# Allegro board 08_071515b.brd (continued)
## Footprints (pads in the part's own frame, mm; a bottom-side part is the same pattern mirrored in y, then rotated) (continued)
LSML208W216H122
  rect 1.168x4.394 smd: 1(-1.651,0) 2(1.651,0)
LSMSQ157H83_A
  rect 0.965x3.708 smd: 1(-1.181,0) 2(1.181,0)
LSMSQ157H122
  rect 0.965x3.708 smd: 1(-1.181,0) 2(1.181,0)
QFN12_2X2_PAD0_7X0_7
  oval 0.279x0.711 smd: 1(-0.75,-0.906) 2(-0.25,-0.906) 3(0.25,-0.906) 4(0.75,-0.906) 7(0.75,0.906) 8(0.25,0.906) 9(-0.25,0.906) 10(-0.75,0.906)
  oval 0.711x0.279 smd: 5(0.906,-0.25) 6(0.906,0.25) 11(-0.906,0.25) 12(-0.906,-0.25)
  rect 0.711x0.711 smd: PAD(0,0)
QFN14_3_5X3_5_PAD2_05X2_05
  oval 0.889x0.305 smd: 1(-1.7,-0.75) 7(1.7,-0.75) 8(1.7,0.75) 14(-1.7,0.75)
  oval 0.305x0.889 smd: 2(-1,-1.7) 3(-0.5,-1.7) 4(0,-1.7) 5(0.5,-1.7) 6(1,-1.7) 9(1,1.7) 10(0.5,1.7) 11(0,1.7) 12(-0.5,1.7) 13(-1,1.7)
  rect 2.057x2.057 smd: PAD(0,0)
QFN18_3X3_PAD1_51X1_7
  oval 0.279x0.711 smd: 1(-1,-1.406) 2(-0.5,-1.406) 3(0,-1.406) 4(0.5,-1.406) 5(1,-1.406) 10(1,1.406) 11(0.5,1.406) 12(0,1.406) 13(-0.5,1.406) 14(-1,1.406)
  oval 0.711x0.279 smd: 6(1.371,-0.75) 7(1.371,-0.25) 8(1.371,0.25) 9(1.371,0.75) 15(-1.371,0.75) 16(-1.371,0.25) 17(-1.371,-0.25) 18(-1.371,-0.75)
  rect 1.499x1.702 smd: PAD(0,0)
QFN24_4X4_PAD2_1X2_1
  oval 0.305x0.991 smd: 1(-1.25,-2) 2(-0.75,-2) 3(-0.25,-2) 4(0.25,-2) 5(0.75,-2) 6(1.25,-2) 13(1.25,2) 14(0.75,2) 15(0.25,2) 16(-0.25,2) 17(-0.75,2) 18(-1.25,2)
  oval 0.991x0.305 smd: 7(2,-1.25) 8(2,-0.75) 9(2,-0.25) 10(2,0.25) 11(2,0.75) 12(2,1.25) 19(-2,1.25) 20(-2,0.75) 21(-2,0.25) 22(-2,-0.25) 23(-2,-0.75) 24(-2,-1.25)
  rect 2.108x2.108 smd: PAD(0,0)
QFN28_5X5_PAD3_5X3_5
  oval 0.305x0.838 smd: 1(-1.5,-2.45) 2(-1,-2.45) 3(-0.5,-2.45) 4(0,-2.45) 5(0.5,-2.45) 6(1,-2.45) 7(1.5,-2.45) 15(1.5,2.45) 16(1,2.45) 17(0.5,2.45) 18(0,2.45) 19(-0.5,2.45) 20(-1,2.45) 21(-1.5,2.45)
  oval 0.838x0.305 smd: 8(2.45,-1.5) 9(2.45,-1) 10(2.45,-0.5) 11(2.45,0) 12(2.45,0.5) 13(2.45,1) 14(2.45,1.5) 22(-2.45,1.5) 23(-2.45,1) 24(-2.45,0.5) 25(-2.45,0) 26(-2.45,-0.5) 27(-2.45,-1) 28(-2.45,-1.5)
  rect 3.505x3.505 smd: PAD(0,0)
R0402
  rect 0.635x0.737 smd: 1(-0.5,0) 2(0.5,0)
R0603
  rect 0.787x0.991 smd: 1(-0.85,0) 2(0.85,0)
R0805
  rect 1.041x1.397 smd: 1(-0.95,0) 2(0.95,0)
RESNET8
  rect 0.533x0.813 smd: 1(-0.89,-0.606) 4(0.89,-0.606) 5(0.89,0.606) 8(-0.89,0.606)
  rect 0.254x0.813 smd: 2(-0.25,-0.606) 3(0.25,-0.606) 6(0.25,0.606) 7(-0.25,0.606)
SC70-5_A
  rect 0.406x0.94 smd: 1(-0.65,-1.1) 2(0,-1.1) 3(0.65,-1.1) 4(0.65,1.1) 5(-0.65,1.1)
SOT23-5L-2
  rect 0.61x1.194 smd: 1(-0.95,-1.15) 2(0,-1.15) 3(0.95,-1.15) 4(0.95,1.15) 5(-0.95,1.15)
SOT23_6-3
  rect 0.635x1.067 smd: 1(-0.95,-1.1) 2(0,-1.1) 3(0.95,-1.1) 4(0.95,1.1) 5(0,1.1) 6(-0.95,1.1)
SOT143A
  rect 1.092x1.27 smd: 1(-0.76,-1)
  rect 0.711x1.27 smd: 2(0.96,-1) 3(0.96,1) 4(-0.96,1)
SWSML165W110H75-G
  rect 0.889x0.991 smd: 1(-2.044,-0.795) 2(-2.044,0.795) 3(2.044,0.795) 4(2.044,-0.795)
  rect 1.702x0.559 smd: 5(0,-1.439)
SWSMSQ394H268
  rect 1.194x2.591 smd: 1(-2.54,-5.995) 2(2.54,5.995) 4(2.54,-5.995) 8(-2.54,5.995) C1(0,-5.995) C2(0,5.995)
TBGA24
  round 0.33 smd: A2(-2,-1) A3(-2,0) A4(-2,1) A5(-2,2) B1(-1,-2) B2(-1,-1) B3(-1,0) B4(-1,1) B5(-1,2) C1(0,-2) C2(0,-1) C3(0,0) C4(0,1) C5(0,2) D1(1,-2) D2(1,-1) D3(1,0) D4(1,1) D5(1,2) E1(2,-2) E2(2,-1) E3(2,0) E4(2,1) E5(2,2)
TSOT-5
  rect 0.508x1.524 smd: 1(-0.95,-1.17) 2(0,-1.17) 3(0.95,-1.17) 4(0.95,1.17) 5(-0.95,1.17)
TSSOP14
  rect 0.432x1.778 smd: 1(-1.95,-2.92) 2(-1.3,-2.92) 3(-0.65,-2.92) 4(0,-2.92) 5(0.65,-2.92) 6(1.3,-2.92) 7(1.95,-2.92) 8(1.95,2.92) 9(1.3,2.92) 10(0.65,2.92) 11(0,2.92) 12(-0.65,2.92) 13(-1.3,2.92) 14(-1.95,2.92)
unnamed#2
  round 4.445 hole 3.175 unplated: (0,0)
YSML79W63H31
  rect 0.61x0.787 smd: 1(-0.905,-0.594) 2(0.905,-0.594) 3(0.905,0.594) 4(-0.905,0.594)
YSML79W63H32
  rect 0.762x0.66 smd: 1(-0.66,-0.508) 2(0.66,-0.508) 3(0.66,0.508) 4(-0.66,0.508)
YSML98W79H35
  rect 1.092x0.991 smd: 1(-0.921,-0.72) 2(0.921,-0.72) 3(0.921,0.72) 4(-0.921,0.72)
YSML126W98H31
  rect 1.397x1.194 smd: 1(-1.1,-0.95) 2(1.1,-0.95) 3(1.1,0.95) 4(-1.1,0.95)

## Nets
DGND: C1.2(N2) C2.2(N2) C3.2(N2) C4.2(N2) C5.2(N2) C6.2(N2) C7.2(N2) C8.2(N2) C9.2(N2) C10.2(N2) C11.2(N2) C12.2(N2) C13.2(N2) C14.2(N2) C15.2(N2) C16.2(N2) C17.2(N2) C18.2(N2) C19.2(N2) C20.2(N2) C21.2(N2) C22.2(N2) C23.2(N2) C24.2(N2) C25.2(N2) C26.2(N2) C27.2(N2) C28.2(N2) C29.2(N2) C30.2(N2) C31.2(N2) C32.2(N2) C33.2(N2) C34.2(N2) C35.2(N2) C36.2(N2) C37.2(N2) C38.2(N2) C40.2(N2) C41.2(N2) C42.2(N2) C43.2(N2) C44.2(N2) C45.2(N2) C46.2(N2) C48.2(N2) C49.2(N2) C50.2(N2) C51.2(N2) C52.2(N2) C53.2(N2) C54.2(N2) C55.2(N2) C56.2(N2) C57.2(N2) C58.2(N2) C59.2(N2) C60.2(N2) C61.2(N2) C62.2(N2) C63.2(N2) C64.2(N2) C65.2(N2) C66.2(N2) C67.2(N2) C68.2(N2) C69.2(N2) C70.2(N2) C71.2(N2) C72.2(N2) C73.2(N2) C74.2(N2) C75.2(N2) C76.2(N2) C77.2(N2) C78.2(N2) C79.2(N2) C80.2(N2) C81.2(N2) C82.2(N2) C83.2(N2) C84.2(N2) C85.2(N2) C86.2(N2) C87.2(N2) C88.2(N2) C89.2(N2) C90.2(N2) C91.2(N2) C92.2(N2) C93.2(N2) C94.2(N2) C95.2(N2) C96.2(N2) C97.2(N2) C98.2(N2) C99.2(N2) C100.2(N2) C101.2(N2) C102.2(N2) C103.2(N2) C104.2(N2) C105.2(N2) C106.2(N2) C107.2(N2) C108.2(N2) C109.2(N2) C110.2(N2) C111.2(N2) C112.2(N2) C113.2(N2) C114.2(N2) C115.2(N2) C116.2(N2) C117.2(N2) C118.2(N2) C119.2(N2) C120.2(N2) C121.2(N2) C122.2(N2) C123.2(N2) C124.2(N2) C125.2(N2) C126.2(N2) C127.2(N2) C128.2(N2) C129.2(N2) C130.2(N2) C131.2(N2) C132.2(N2) C133.2(N2) C134.2(N2) C135.2(N2) C136.2(N2) C137.2(N2) C138.2(N2) C139.2(N2) C140.2(N2) C141.2(N2) C142.2(N2) C143.2(N2) C144.2(N2) C145.2(N2) C146.2(N2) C147.2(N2) C148.2(N2) C149.2(N2) C150.2(N2) C151.2(N2) C152.2(N2) C153.2(N2) C154.2(N2) C155.2(N2) C156.2(N2) C157.2(N2) C158.2(N2) C159.2(N2) C160.2(N2) C161.2(N2) C162.2(N2) C163.2(N2) C164.2(N2) C165.2(N2) C166.2(N2) C168.2(N2) C170.2(N2) C171.2(N2) C172.1 C173.2(N2) C174.2(N2) C175.2(N2) C176.2(N2) C177.2(N2) C178.2(N2) C179.2(N2) C180.2(N2) C181.2(N2) C182.2(N2) C183.2(N2) C184.2(N2) C185.2(N2) C186.2(N2) C187.2(N2) C188.2(N2) C189.2(N2) C190.2(N2) C191.2(N2) C192.2(N2) C193.2(N2) C194.2(N2) C196.2(N2) C197.2(N2) C198.2(N2) C199.1 C200.1 C201.2(N2) C202.2(N2) C203.2(N2) C204.2(N2) C205.2(N2) C206.2(N2) C211.2(N2) C212.2(N2) C213.2(N2) C214.2(N2) C215.2(N2) C216.2(N2) C217.2(N2) C218.2(N2) C219.2(N2) C221.2(N2) C222.2(N2) C223.2(N2) C224.2(N2) C225.2(N2) C226.2(N2) C227.2(N2) C228.2(N2) C229.2(N2) C230.2(N2) C231.2(N2) C232.2(N2) C233.1 C234.1 C235.1 C236.1 C237.1 C238.1 C239.2(N2) C240.2(N2) C242.2(N2) C243.2(N2) C244.2(N2) C245.2(N2) C246.2(N2) C247.2(N2) C248.2(N2) C251.2(N2) C252.2(N2) C253.2(N2) C254.2(N2) D1.2 D1.5 D15.A(P) D17.2 FL1.2 FL2.2 FL3.2 J1.1 J1.2 J1.43 J1.44 J1.45 J1.46 J1.55 J1.56 J1.87 J1.94 J2.1 J2.2 J2.24 J2.25 J2.48 J2.51 J2.62 J2.68 J2.71 J2.79 J2.80 J3.1 J3.2 J3.22 J3.25 J3.36 J3.39 J3.41 J3.46 J3.60 J3.76 J3.85 J3.90 J3.98 J3.100 P1.A1 P1.A12 P1.B1 P1.B12 P1.GND1 P1.GND2 P6.3 P6.5 R1.2(N2) R4.2(N2) R6.2(N2) R10.2(N2) R17.2(N2) R21.2(N2) R23.2(N2) R24.2(N2) R25.2(N2) R26.2(N2) R34.2(N2) R36.2(N2) R38.2(N2) R50.2(N2) R54.2(N2) R56.2(N2) R57.2(N2) R58.1 R66.2(N2) R67.1 R77.2(N2) R79.2(N2) R80.2(N2) R82.2(N2) R84.2(N2) R88.2(N2) R91.2(N2) R93.2(N2) R95.1 R98.2(N2) R103.2(N2) R106.2(N2) R109.2(N2) S2.1 S2.4 S2.5(N5) U1.A1 U1.A20 U1.B1 U1.B2 U1.B19 U1.C3 U1.C4 U1.C5 U1.C6 U1.C14 U1.C15 U1.C16 U1.C17 U1.C18 U1.D2 U1.D4 U1.D5 U1.D6 U1.D7 U1.D12 U1.D13 U1.D14 U1.D15 U1.D16 U1.D17 U1.D18 U1.E3 U1.E18 U1.F3 U1.F18 U1.G3 U1.G18 U1.H2 U1.H3 U1.H8 U1.H9 U1.H10 U1.H11 U1.H12 U1.H13 U1.H18 U1.J3 U1.J8 U1.J9 U1.J10 U1.J11 U1.J12 U1.J13 U1.J18 U1.K1 U1.K2 U1.K3 U1.K8 U1.K9 U1.K10 U1.K11 U1.K12 U1.K13 U1.K17 U1.K18 U1.K19 U1.K20 U1.L2 U1.L3 U1.L8 U1.L9 U1.L10 U1.L11 U1.L12 U1.L13 U1.L16 U1.L17 U1.M1 U1.M2 U1.M8 U1.M9 U1.M10 U1.M11 U1.M12 U1.M13 U1.M17 U1.M18 U1.N2 U1.N8 U1.N9 U1.N10 U1.N11 U1.N12 U1.N13 U1.N17 U1.N18 U1.P1 U1.P17 U1.P19 U1.P20 U1.R2 U1.R17 U1.T1 U1.T4 U1.T17(GND_99) U1.U1 U1.U4 U1.U5 U1.U16 U1.U17 U1.V3 U1.V4 U1.V15 U1.V16 U1.V18 U1.W1 U1.W2 U1.W19 U1.W20 U1.Y1 U1.Y2 U1.Y5 U1.Y7 U1.Y13 U1.Y16 U1.Y19 U1.Y20 U2.3 U2.8 U2.PAD U3.3 U4.B3 U5.3 U7.7 U8.A9 U8.B1 U8.B3 U8.B9 U8.D1 U8.D8 U8.E1 U8.E2 U8.E8 U8.F9 U8.G1 U8.G8 U8.G9 U8.J2 U8.J8 U8.M1 U8.M9 U8.P1 U8.P9 U8.T1 U8.T9 U9.3 U10.3 U11.3 U13.3 U14.1 U15.3 U15.PAD U16.2 U16.5 U16.10 U16.PAD U17.1 U17.4 U17.7 U17.PAD U18.2 U19.3 U20.3 U21.3 U22.7 U22.PAD U23.7 U23.PAD U24.19 U24.PAD U25.B3 U25.C1 U25.E5(VSSQ_2) U26.2 U26.5(WP) U27.7 U27.PAD U28.7 U28.PAD U29.7 U29.PAD U30.7 U30.PAD VR1.4 VR1.13 VR1.PAD Y1.2 Y1.4 Y2.2 Y4.2 Y5.2 Y6.2
VDD_CONNECTOR: J3.97 J3.99 JP1.3(N3)
VDD_DMC: C1.1 C2.1 C3.1 C5.1 C6.1 C7.1 C8.1 C11.1 C13.1 C39.1 C48.1 C53.1 C58.1 C63.1 C69.1 C74.1 C79.1 C84.1 C89.1 C94.1 C98.1 C102.1 C106.1 C110.1 C114.1 C118.1 C122.1 C126.1 C130.1 C134.1 C138.1 C142.1 C146.1 C150.1 C153.1 C156.1 C162.1 C220.1 C224.1 C227.1 C230.1 J3.92 L4.2(N2) R8.1 R9.1 R108.1 TP3.1(N1) U1.F6 U1.F7 U1.F8 U1.F9 U1.F10 U1.F11 U1.F12 U1.F13 U1.F14 U1.F15 U1.G6 U1.G7 U1.G8 U1.G9 U1.G12 U1.G13 U1.G14 U1.G15 U1.H6 U1.H7 U1.H14 U1.H15 U1.J6 U1.J7 U1.K7 U2.4 U8.A1 U8.A8 U8.B2 U8.C1 U8.C9 U8.D2 U8.D9 U8.E9 U8.F1 U8.G7 U8.H2 U8.H9 U8.K2 U8.K8 U8.N1 U8.N9 U8.R1 U8.R9
VDD_EXT: C38.1 C49.1 C54.1 C59.1 C64.1 C70.1 C75.1 C80.1 C85.1 C90.1 C95.1 C99.1 C103.1 C107.1 C111.1 C115.1 C119.1 C123.1 C127.1 C131.1 C135.1 C139.1 C143.1 C147.1 C151.1 C154.1 C157.1 C159.1 C160.1 C163.1 C170.1 C171.1 C172.2(N2) C173.1 C174.1 C175.1 C176.1 C179.1 C180.1 C181.1 C182.1 C189.1 C191.1 C192.1 C194.1 C197.1 C199.2(N2) C200.2(N2) C210.1 C213.1 C215.1 C216.1 C218.1 C219.1 C222.1 C225.1 C228.1 C232.1 C233.2(N2) C234.2(N2) C235.2(N2) C236.2(N2) C237.2(N2) C238.2(N2) C247.1 C248.1 C251.1 C252.1 C253.1 C254.1 DS1.A(P) DS2.A(P) DS3.A(P) DS4.A(P) DS5.A(P) DS6.A(P) L3.2(N2) P6.1 R5.1 R14.1 R15.1 R19.1 R31.1 R32.1 R33.1 R35.1 R37.1 R39.2(N2) R40.2(N2) R41.1 R45.1 R46.1 R47.1 R48.1 R51.1 R53.1 R55.1 R60.1 R61.1 R62.1 R63.1 R64.1 R70.1 R71.1 R75.1 R78.1 R81.1 R83.1 R104.2(N2) R105.1 R121.2(N2) R122.2(N2) R136.1 R137.1 R139.1 R140.1 R143.1 S1.C1 S1.C2 TP1.1(N1) U1.D8 U1.D9 U1.D10 U1.D11 U1.K4 U1.L4 U1.M4 U1.M16 U1.N4 U1.N16 U1.P4 U1.P16 U1.R4 U1.R16 U1.T5 U1.T16 U1.U6 U1.U7 U1.U8 U1.U9 U1.U10 U1.U11 U1.U12 U1.U13 U1.U14 U1.U15 U2.2 U2.7 U2.10 U3.5(VCC) U4.B4 U5.5(VCC) U7.14(VCC) U9.5(VCC) U10.5(VCC) U11.5 U13.5 U14.4(VCC) U16.3 U16.4 U16.11 U16.12(VIN_4) U16.13 U16.15 U17.3 U17.8(VIN_2) U17.10 U18.1 U18.3 U19.5(VCC) U20.5(VCC) U21.5(VCC) U22.14(VCC) U23.14(VCC) U24.21(VCC) U25.B4 U25.D1 U25.E4 U26.4 U27.14(VCC) U28.14(VCC) U29.14(VCC) U30.14(VCC) VR1.2 Y4.4(VCC) Y5.4(VDD) Y6.4(VDD)
VDD_INPUT: C190.1 C196.1 C198.1 C203.1 C205.1 JP1.2 R96.1 VR1.6 VR1.11(VIN_2)
VDD_INT: C50.1 C51.1 C55.1 C56.1 C60.1 C61.1 C65.1 C66.1 C68.1 C71.1 C73.1 C76.1 C78.1 C81.1 C83.1 C86.1 C88.1 C91.1 C93.1 C96.1 C100.1 C104.1 C108.1 C112.1 C116.1 C120.1 C124.1 C128.1 C132.1 C136.1 C140.1 C144.1 C148.1 C152.1 C155.1 C161.1 C164.1 C165.1 C208.1 C209.2(N2) C211.1 C212.1 C214.1 C217.1 C221.1 C223.1 C226.1 C229.1 L1.1 L2.2(N2) R44.1 R99.2(N2) R101.1 R107.2(N2) TP2.1(N1) U1.E4 U1.E5 U1.E6 U1.E7 U1.E8 U1.E9 U1.E10 U1.E11 U1.E12 U1.E13 U1.E14 U1.E15 U1.E16 U1.E17 U1.F4 U1.F5 U1.F16 U1.F17 U1.G4 U1.G5 U1.G16 U1.G17 U1.H4 U1.H5 U1.H16 U1.H17 U1.J5 U1.J14 U1.J15 U1.J16 U1.J17 U1.K5 U1.K14 U1.K15 U1.K16 U1.L5 U1.L14 U1.L15 U1.M5 U1.M6 U1.M14 U1.N6 U1.N7 U1.N14 U1.P6 U1.P7 U1.P8 U1.P9 U1.P10 U1.P11 U1.P12 U1.P13 U1.P14 U1.R6 U1.R7 U1.R8 U1.R9 U1.R10 U1.R11 U1.R12 U1.R13 U1.R14
VDD_PLL: C46.1 C47.1 C242.1 C243.1 C244.1 L1.2(N2) U1.K6 U1.L6 U1.L7 U1.M7
VDD_REF: C52.1 C57.1 C62.1 C67.1 C72.1 C77.1 C82.1 C87.1 C92.1 C97.1 C101.1 C105.1 C109.1 C113.1 C117.1 C121.1 C125.1 C129.1 C133.1 C137.1 C141.1 C145.1 C149.1 C201.1 C231.1 FL2.1 FL3.1 R16.1 R42.1 R43.1 R113.1 TP4.1(N1) U1.G10 U1.G11 U1.M15 U1.N15 U1.P5 U1.P15 U1.R5 U1.R15 U1.T6 U1.T7 U1.T8 U1.T9 U1.T10 U1.T11 U1.T12 U1.T13 U1.T14 U1.T15 U18.5(VOUT) Y2.4(VDD)
AUDIO_CLK: J3.40 R141.2(N2)
CLK1: J3.42 R142.2(N2)
CLK2: J3.44 R144.2(N2)
CON_RESET_IN*: J3.96 R62.2(N2) U11.2
DAI0_PIN01: J1.3 U1.Y8
DAI0_PIN02: J1.5 U1.V9
DAI0_PIN03: J1.7 U1.W9
DAI0_PIN04: J1.9 U1.Y9
DAI0_PIN05: J1.11 U1.W10
DAI0_PIN06: J1.13 U1.V10
DAI0_PIN07: J1.15 U1.Y10
DAI0_PIN08: J1.17 U1.W11
DAI0_PIN09: J1.19 U1.V11
DAI0_PIN10: J1.21 U1.Y11
DAI0_PIN11: J1.23 U1.Y12
DAI0_PIN12: J1.25 U1.W12
DAI0_PIN19: J1.39 U1.W13
DAI0_PIN20: J1.41 U1.V12
DAI1_PIN01: J1.4 U1.R20
DAI1_PIN02: J1.6 U1.P18
DAI1_PIN03: J1.8 U1.R18
DAI1_PIN04: J1.10 U1.T20
DAI1_PIN05: J1.12 U1.U20
DAI1_PIN06: J1.14 U1.T19
DAI1_PIN07: J1.16 U1.U19
DAI1_PIN08: J1.18(N9) U1.R19
DAI1_PIN09: J1.20 U1.T18
DAI1_PIN10: J1.22 U1.U18
DAI1_PIN11: J1.24 U1.V19
DAI1_PIN12: J1.26 U1.V20
DAI1_PIN19: J1.40 U1.V17
DAI1_PIN20: J1.42 U1.W18
DMC0_A00: RN1.1 U1.D19 U8.N3
DMC0_A01: RN3.2 U1.D20 U8.P7
DMC0_A02: RN2.2 U1.C20 U8.P3
DMC0_A03: RN5.2 U1.C19 U8.N2
DMC0_A04: RN4.1 U1.A19 U8.P8
DMC0_A05: RN5.3 U1.B20 U8.P2
DMC0_A06: RN3.4 U1.B18 U8.R8
DMC0_A07: RN5.4 U1.A18 U8.R2
DMC0_A08: RN3.3 U1.A16 U8.T8
DMC0_A09: RN2.4 U1.B16 U8.R3
DMC0_A10: RN7.1 U1.A15 U8.L7
DMC0_A11: RN1.4 U1.B15 U8.R7
DMC0_A12: RN4.2 U1.B14 U8.N7
DMC0_A13: RN2.3 U1.A14 U8.T3
DMC0_A14: RN3.1 U1.A13 U8.T7
DMC0_A15: RN4.4 U1.B13 U8.M7
DMC0_BA0: RN5.1 U1.B17 U8.M2
DMC0_BA1: RN4.3 U1.A17 U8.N8
DMC0_BA2: RN1.2 U1.E19 U8.M3
DMC0_CAS*: RN6.3 U1.E20 U8.K3
DMC0_CK: R3.1 U1.J20 U8.J7
DMC0_CK*: R3.2(N2) U1.J19 U8.K7
DMC0_CKE: RN7.2 U1.H20 U8.K9
DMC0_CS0*: RN6.4 U1.F20 U8.L2
DMC0_DQ00: U1.J2 U8.E3
DMC0_DQ01: U1.E1 U8.F7
DMC0_DQ02: U1.H1 U8.F2
DMC0_DQ03: U1.D1 U8.F8
DMC0_DQ04: U1.G2 U8.H3
DMC0_DQ05: U1.E2 U8.H8
DMC0_DQ06: U1.J1 U8.G2
DMC0_DQ07: U1.G1 U8.H7
DMC0_DQ08: U1.C2 U8.D7
DMC0_DQ09: U1.B6 U8.C3
DMC0_DQ10: U1.B5 U8.C8
DMC0_DQ11: U1.A5 U8.C2
DMC0_DQ12: U1.A2 U8.A7
DMC0_DQ13: U1.B3 U8.A2
DMC0_DQ14: U1.D3 U8.B8
DMC0_DQ15: U1.A3 U8.A3
DMC0_LDM: U1.C1 U8.E7
DMC0_LDQS: U1.F2 U8.F3
DMC0_LDQS*: U1.F1 U8.G3
DMC0_ODT: RN6.2 U1.H19 U8.K1
DMC0_RAS*: RN6.1 U1.F19 U8.J3
DMC0_RESET*: R8.2(N2) RN2.1 U1.B12 U8.T2
DMC0_RZQ: R1.1 U1.G19
DMC0_UDM: U1.A6 U8.D3
DMC0_UDQS: U1.B4 U8.C7
DMC0_UDQS*: U1.A4 U8.B7
DMC0_VREF: C4.1 R2.1 R7.2(N2) R11.2(N2)
DMC0_WE*: RN1.3 U1.A12 U8.L3
FPLL_VDDHV: C239.1 C240.1 FL3.3(OUT) U1.N5
HADC0_VIN0: J1.47 U1.N19
HADC0_VIN1: J1.49 U1.N20
HADC0_VIN2: J1.51 U1.M19
HADC0_VIN3: J1.53 U1.M20
ID0: J2.76 R136.2(N2) U26.1
ID1: J2.78 R137.2(N2) U26.3
INTVCC: C206.1 R94.2(N2) R100.2(N2) VR1.3
JTG0_TCK/SWCLK: J3.50 P6.4 U1.B11
JTG0_TD0/SW0: J3.52 P6.6 U1.C11
JTG0_TDI: J3.54 P6.8 U1.C13
JTG0_TMS/SWDIO: J3.48 P6.2 U1.C12
JTG0_TRST*: J3.56 P6.9 R78.2(N2) R79.1 U1.A10
LTC3310_EN: R92.2(N2) U16.1
PA_00/SPI2_MISO/XSPI0_MISO/PWM0_AH/SMC0_D00: U1.N3 U22.6 U23.6
PA_00/SPI2_MISO/XSPI0_MISO/PWM0_AH/SMC0_D00_Z: J2.3 U23.5
PA_01/SPI2_MOSI/XSPI0_MOSI/PWM0_AL/SMC0_D01: U1.P3 U22.3 U23.3
PA_01/SPI2_MOSI/XSPI0_MOSI/PWM0_AL/SMC0_D01_Z: J2.5 U23.2
PA_02/SPI2_D2/XSPI0_D2/TWI3_SCL/SMC0_D02/TM0_ACLK3: U1.P2 U22.8 U23.8
PA_02/SPI2_D2/XSPI0_D2/TWI3_SCL/SMC0_D02/TM0_ACLK3_Z: J2.7 U23.9
PA_03/SPI2_D3/XSPI0_D3/TWI3_SDA/SMC0_D03: U1.R3 U22.12 U23.12
PA_03/SPI2_D3/XSPI0_D3/TWI3_SDA/SMC0_D03_Z: J2.9 U23.11
PA_04/SPI2_CLK/XSPI0_CLK/PWM0_BH/SMC0_D04: U1.R1 U27.3 U28.3
PA_04/SPI2_CLK/XSPI0_CLK/PWM0_BH/SMC0_D04_Z: J2.11 U28.2
PA_05/SPI2_SEL1B/XSPI0_SEL1B/FPLL_DBG_LOCK/SMC0_D05/SPI2_SSB: U1.T2 U27.6 U28.6
PA_05/SPI2_SEL1B/XSPI0_SEL1B/FPLL_DBG_LOCK/SMC0_D05/SPI2_SSB_Z: J2.13 U28.5
PA_06/SPI0_CLK/UART0_TXB/XSPI0_D4/SMC0_D06/TM0_ACLK1: U1.T3 U7.9 U29.3 U30.3
PA_06/SPI0_CLK/UART0_TXB/XSPI0_D4/SMC0_D06/TM0_ACLK1_Z: J2.4 J2.15 J2.43 U30.2
PA_07/SPI0_MISO/UART0_RXB/XSPI0_D5/SMC0_D07/TM0_ACI0: U1.V1 U7.12 U29.6 U30.6
PA_07/SPI0_MISO/UART0_RXB/XSPI0_D5/SMC0_D07/TM0_ACI0_Z: J2.6 J2.17 J2.45 U30.5
PA_08/SPI0_MOSI/UART0_RTSB/XSPI0_D6/SMC0_D08/TM0_ACLK2: U1.U3 U7.2 U29.8 U30.8
PA_08/SPI0_MOSI/UART0_RTSB/XSPI0_D6/SMC0_D08/TM0_ACLK2_Z: J2.8 J2.19 J2.47 U30.9
PA_09/SPI0_SEL1B/UART0_CTSB/XSPI0_D7/SMC0_D09/SPI0_SSB: U1.V2 U7.5 U29.12 U30.12
PA_09/SPI0_SEL1B/UART0_CTSB/XSPI0_D7/SMC0_D09/SPI0_SSB_Z: J2.10 J2.21 J2.49 U30.11
PA_10/TWI0_SCL/SPI1_CLK/TM0_TMR0/SMC0_D10: J2.14 J2.31 R49.1 U1.U2
PA_11/TWI0_SDA/SPI1_MISO/HADC_EOC_OUT/SMC0_D11/TM0_ACI4: J2.16 J2.33 R52.2(N2) U1.V8
PA_12/FLG0/SPI1_MOSI/TM0_TMR1/SMC0_D12: J2.18(N9) U1.W6 U4.D3
PA_13/FLG1/SPI1_SEL1B/TM0_TMR2/SMC0_D13/SPI1_SSB: J2.20 U1.Y6 U9.2
PA_14/TWI2_SCL/SPI1_D2/UART1_RXB/SMC0_D14/TM0_ACI1: J2.32 U1.W7 U10.2 U21.2
PA_15/TWI2_SDA/SPI1_D3/UART1_TXB/SMC0_D15/FPLL_REF_CLK: J2.34 U1.W8 U5.2 U20.2
PB_00/MLB0_DAT/TWI1_SCL/UART1_RTSB/SMC0_AMS0B/TM0_ACI3: R30.1 U1.A7 U3.2
PB_00/MLB0_DAT/TWI1_SCL/UART1_RTSB/SMC0_AMS0B/TM0_ACI3_Z: J1.100 J2.35 J2.36 U3.4
PB_01/MLB0_SIG/TWI1_SDA/UART1_CTSB/SMC0_AREB/TM0_CLK: R29.1 U1.C9 U19.2
PB_01/MLB0_SIG/TWI1_SDA/UART1_CTSB/SMC0_AREB/TM0_CLK_Z: J1.98 J2.37 J2.38 U19.4
PB_02/MLB0_CLK/FLG3/LP1_ACK/SMC0_AWEB/TM0_ACLK4: J1.96 J2.98 U1.B8
PB_03/TM0_TMR3/FLG2/SPI2_SEL2B/SMC0_ADDR1/CNT0_UD: J1.88 J2.23 J2.50 U1.C7
PB_04/TM0_TMR4/SPI1_RDY/LP0_ACK/SMC0_ADDR2/CNT0_ZM: J1.90 J2.28 J2.97 U1.B7
PB_05/TM0_TMR5/SPI2_RDY/SPI0_SEL2B/SMC0_ADDR3/CNT0_DG: J1.92 J2.12 J2.30 J2.52 U1.C8
PB_06/LP0_CLK/SPI1_SEL5B/PWM0_BL/TRACE0_CLK: J2.99 U1.V5
PB_07/LP0_D0/SPI2_SEL5B/TRACE0_D00: J2.95 U1.W4
PB_08/LP0_D1/SPI1_SEL7B/TM0_TMR6/TRACE0_D01: J2.93 U1.W3
PB_09/LP0_D2/SPI2_SEL7B/TM0_TMR7/TRACE0_D02: J2.91 U1.V6
PB_10/LP0_D3/SPI1_SEL2B/PWM0_CH/TRACE0_D03: J2.22 J2.89 U1.Y3
PB_11/LP0_D4/SPI0_RDY/PWM0_CL/UART2_RXB/TM0_ACI2: J2.26 J2.42 J2.87 U1.Y4
PB_12/LP0_D5/SPI2_SEL3B/PWM0_DH/UART2_TXB: J2.40 J2.85 U1.V7
PB_13/LP0_D6/SPI1_SEL3B/XSPI0_DQSB_RWDS/UART2_RTSB: J2.44 J2.83 U1.W5 U27.12 U28.12
PB_13/LP0_D6/SPI1_SEL3B/XSPI0_DQSB_RWDS/UART2_RTSB_Z: J2.27 U28.11
PB_14/LP0_D7/SPI0_SEL3B/PWM0_DL/UART2_CTSB: J2.46 J2.81 U1.Y14
PB_15/LP1_D0/SPI0_SEL4B/SMC0_ADDR4: J2.96 U1.W14
PC_00/LP1_D1/TWI4_SCL/TRACE0_D04/SPI1_SEL4B: J2.94 U1.V13
PC_01/LP1_D2/TWI4_SDA/TRACE0_D05/SPI2_SEL4B: J2.92 U1.W15
PC_02/LP1_D3/TWI5_SCL/TRACE0_D06/SPI1_SEL6B: J2.90 U1.Y15
PC_03/LP1_D4/TWI5_SDA/TRACE0_D07/SPI2_SEL6B: J2.88 U1.W16
PC_04/LP1_D5/XSPI0_SEL2B/PWM0_SYNC/SMC0_ADDR5: U1.Y17 U27.8 U28.8
PC_04/LP1_D5/XSPI0_SEL2B/PWM0_SYNC/SMC0_ADDR5_Z: J2.86 U28.9
PC_05/LP1_D6/XSPI0_SEL3B/TM0_TMR8/SMC0_ADDR6: J2.84 U1.V14
PC_06/LP1_D7/SPI1_RDY/PWM0_TRIPB/SMC0_ADDR7: J2.82 U1.W17
PC_07/LP1_CLK/TM0_TMR9/SYS_FAULT*: J2.100 R23.1 U1.Y18
PG1: R100.1 U17.2 VR1.1
PG2: R92.1 R104.1 U17.11
SOM_TWI1_EN*: R19.2(N2) R21.1 U3.1 U19.1 U24.10
SOM_TWI2_EN*: R33.2(N2) R34.1 U20.1 U21.1 U24.9
SOM_XSPI_EN*: R37.2(N2) R38.1 U23.1 U23.4 U23.10 U23.13 U24.12 U28.1 U28.4 U28.10 U28.13 U30.1 U30.4 U30.10 U30.13
SPI1D2_D3_EN*: R53.2(N2) R54.1 U5.1 U10.1 U24.6
SPI1IFLASH_CS_EN*: R55.2(N2) R56.1 U9.1 U24.5
SPIFLASH_CS*: R46.2(N2) U4.C2 U9.4
SPIFLASH_SPI1D2: R48.2(N2) U4.C4(WP#/(IO2)) U10.4
SPIFLASH_SPI1D3: R47.2(N2) U4.D4 U5.4
SYS_BMODE0: R24.1 S1.1 U1.B10
SYS_BMODE1: R25.1 S1.2 U1.B9
SYS_BMODE2: R26.1 S1.4 U1.A8
SYS_CLKIN0: R27.2(N2) R123.2(N2) U1.N1
SYS_CLKOUT: J3.38 U1.M3
SYS_FAULT*: J3.88 R59.2(N2) R60.2(N2) U1.A11
SYS_HWRST*: J3.94 R57.1 R64.2(N2) R73.2(N2) R75.2(N2) U1.A9 U4.A4 U14.2 U24.20 U25.A4
SYS_RESOUT*: R61.2(N2) U1.C10
SYS_XTAL0: R18.1 U1.L1
TARGET_RESET*: J3.58 R63.2(N2) R85.2(N2) U11.1
TWI1_SCL: R30.2(N2) R32.2(N2) U24.23
TWI1_SDA: R29.2(N2) R31.2(N2) U24.22
TWI2_SCL: J2.39 R13.2(N2) R15.2(N2)
TWI2_SDA: J2.41 R12.2(N2) R14.2(N2)
UART0_EN*: R81.2(N2) R82.1 U7.10 U7.13 U24.7
UART0_FLOW_EN*: R83.2(N2) R84.1 U7.1 U7.4 U24.8
UART_3V3_IO: C187.1 C188.1 DS7.A(P) DS8.A(P) R86.1 R87.1 R124.1 U15.6
UNNAMED_3_ADSP21835_I66_HADC0VREFN: R58.2(N2) U1.L18
UNNAMED_3_ADSP21835_I66_HADC0VREFP: C177.1 C178.1 FL2.3(OUT) U1.L20
UNNAMED_3_DIOLED_I14_N: DS6.C R59.1
UNNAMED_4_741G125_I12_B: R12.1 U20.4
UNNAMED_4_741G125_I14_B: R13.1 U21.4
UNNAMED_5_CAP_I8_N2: C47.2(N2) R17.1
UNNAMED_5_CAP_I13_N1: C44.1 C45.1 FL1.3(OUT) U1.L19
UNNAMED_5_FLTR3P_I3_IN: FL1.1 R16.2(N2)
UNNAMED_7_CAP_I7_N1: C166.1 R20.2(N2) Y1.1
UNNAMED_7_CAP_I12_N1: C168.1 R22.2(N2) R27.1 Y1.3(IN/OUT2)
UNNAMED_7_RES_I10_N2: R18.2(N2) R20.1 R22.1
UNNAMED_7_RES_I25_N2: R140.2(N2) Y5.1
UNNAMED_7_RES_I31_N2: R139.2(N2) Y4.1
UNNAMED_7_RES_I35_N2: R143.2(N2) Y6.1
UNNAMED_7_RES_I51_N2: R113.2(N2) Y2.1
UNNAMED_7_RES_I59_N1: R141.1 Y4.3
UNNAMED_7_RES_I60_N1: R142.1 Y5.3
UNNAMED_7_RES_I61_N1: R144.1 Y6.3
UNNAMED_7_RES_I62_N1: R123.1 Y2.3
UNNAMED_8_ICS71KLXXX_I51_CK: R110.2(N2) U25.B2
UNNAMED_8_ICS71KLXXX_I51_CS1: R68.2(N2) U25.C2
UNNAMED_8_ICS71KLXXX_I51_CS2: R69.2(N2) U25.A3
UNNAMED_8_ICS71KLXXX_I51_DQ0: R119.1 U25.D3
UNNAMED_8_ICS71KLXXX_I51_DQ1: R118.1 U25.D2
UNNAMED_8_ICS71KLXXX_I51_DQ2: R117.1 U25.C4
UNNAMED_8_ICS71KLXXX_I51_DQ3: R116.1 U25.D4
UNNAMED_8_ICS71KLXXX_I51_DQ4: R115.1 U25.D5
UNNAMED_8_ICS71KLXXX_I51_DQ5: R114.1 U25.E3
UNNAMED_8_ICS71KLXXX_I51_DQ6: R112.1 U25.E2
UNNAMED_8_ICS71KLXXX_I51_DQ7: R111.1 U25.E1
UNNAMED_8_ICS71KLXXX_I51_RWDS: R120.1 U25.C3
UNNAMED_9_CAP_I3_N1: C185.1 C186.1 E1.2(N2) R65.1 U15.7(VREGIN)
UNNAMED_9_CMOSPI3C3125_I11_B0: R86.2(N2) U7.3 U15.23
UNNAMED_9_CMOSPI3C3125_I11_B1: R87.2(N2) U7.6 U15.24
UNNAMED_9_CMOSPI3C3125_I11_B2: U7.8 U15.25
UNNAMED_9_CMOSPI3C3125_I11_B3: U7.11 U15.26
UNNAMED_9_CN10PODDEVEN_I35_N5: P6.10(N5) R85.1
UNNAMED_9_DIOLED_I22_N: DS7.C R89.1
UNNAMED_9_DIOLED_I23_N: DS8.C R90.1
UNNAMED_9_ICCP2102NA_I49_GPIO: R89.2(N2) U15.18
UNNAMED_9_ICCP2102NA_I49_GPIO_1: R90.2(N2) U15.19
UNNAMED_9_ICCP2102NA_I49_RSTBN: R124.2(N2) U15.9
UNNAMED_9_ICCP2102NA_I49_VBUS: R65.2(N2) R88.1 U15.8
UNNAMED_10_7408V3_I4_Y: U11.4(Y) U13.1
UNNAMED_10_7408V3_I7_B: R70.2(N2) S2.2 S2.3 U13.2
UNNAMED_10_7408V3_I7_Y: R71.2(N2) U13.4(Y) U14.3
UNNAMED_10_ADP5587_I68_C7: R72.2(N2) U24.16
UNNAMED_10_ADP5587_I68_C8: R74.2(N2) U24.17
UNNAMED_10_ADP5587_I68_C9: R76.2(N2) U24.18
UNNAMED_10_DIOLED_I20_N: DS5.C R73.1
UNNAMED_10_DIOLED_I27_N: DS4.C R77.1
UNNAMED_10_DIOLED_I69_N: DS3.C R72.1
UNNAMED_10_DIOLED_I71_N: DS2.C R74.1
UNNAMED_10_DIOLED_I73_N: DS1.C R76.1
UNNAMED_12_CN100PV2_I10_N44: J3.87 R41.2(N2)
UNNAMED_12_CN100PV2_I10_N45: J3.89 R42.2(N2)
UNNAMED_12_CN100PV2_I10_N46: J3.91 R43.2(N2)
UNNAMED_12_CN100PV2_I10_N47: J3.93 R44.2(N2)
UNNAMED_12_CN100PV2_I10_N48: J3.95 R45.2(N2)
UNNAMED_13_CAP_I3_N1: C184.1 P1.SH1 P1.SH2 P1.SH3 P1.SH4 P1.SH5 P1.SH6 R80.1
UNNAMED_13_CN24PAB2GND6SHLD_I10_N5: D17.3 P1.A5 R6.1
UNNAMED_13_CN24PAB2GND6SHLD_I11_N5: D17.1 P1.B5 R66.1
UNNAMED_14_ADLT8636_I23_BST: C207.1 VR1.7
UNNAMED_14_ADLT8636_I23_EN: R95.2(N2) R96.2(N2) VR1.14
UNNAMED_14_ADLT8636_I23_FB1: C210.2(N2) R105.2(N2) R106.1 VR1.19 VR1.20
UNNAMED_14_ADLT8636_I23_RT: R98.1 VR1.17
UNNAMED_14_ADLT8636_I23_SW1: C207.2(N2) L3.1 VR1.8 VR1.9 VR1.10
UNNAMED_14_ADLT8636_I23_SYNC: R93.1 R94.1 VR1.15
UNNAMED_14_ADLT8636_I23_TR: C204.1 VR1.18
UNNAMED_14_ADLTC3307_I51_FB: C220.2(N2) R108.2(N2) R109.1 U17.12
UNNAMED_14_ADLTC3307_I51_MODE: R5.2(N2) U17.9
UNNAMED_14_ADLTC3307_I51_SW1: L4.1 U17.5 U17.6
UNNAMED_14_ADLTC3310_I15_FB: C208.2(N2) C209.1 R97.2(N2) R101.2(N2) R102.1 R107.1 U16.18
UNNAMED_14_ADLTC3310_I15_ITH: C193.1 C195.1 R97.1 U16.17
UNNAMED_14_ADLTC3310_I15_PGOOD: R99.1 U16.14
UNNAMED_14_ADLTC3310_I15_SSTT: C202.1 U16.16
UNNAMED_14_ADLTC3310_I15_SW1: L2.1 U16.6 U16.7 U16.8 U16.9
UNNAMED_14_CAP_I9_N2: C195.2(N2) R91.1
UNNAMED_14_RES_I39_N1: R102.2(N2) R103.1
UNNAMED_17_ADSP21835_I205_DMC0VREF1: R2.2(N2) U1.G20 U1.J4
UNNAMED_17_CAP_I42_N1: C27.1 C36.1 R7.1 U2.1
UNNAMED_17_CAP_I61_N1: C28.1 C30.1 C32.1 C34.1 C39.2(N2) C40.1 R9.2(N2) R10.1 R11.1 U8.H1 U8.M8
UNNAMED_17_ICIS4XTR16256_I45_ZQ: R4.1 U8.L8(ZQ)
UNNAMED_18_ICIS25XP512M_I1_SCK: R49.2(N2) R50.1 U4.B2
UNNAMED_18_ICIS25XP512M_I1_SO: R51.2(N2) R52.1 U4.D2
USB_DM: D1.3 P1.A7 P1.B7 U15.5
USB_DP: D1.4 P1.A6 P1.B6 U15.4
USB_TYPEC: C158.1 C183.1 D1.1 D15.C E1.1 JP1.1 P1.A4 P1.A9 P1.B4 P1.B9(N9)
VTT: C9.1 C10.1 C12.1 C14.1 C15.1 C16.1 C17.1 C18.1 C19.1 C20.1 C21.1 C22.1 C23.1 C24.1 C25.1 C26.1 C29.1 C31.1 C33.1 C35.1 C37.1 C41.1 C42.1 C43.1 C245.1 C246.1 RN1.5 RN1.6 RN1.7 RN1.8(N8) RN2.5 RN2.6 RN2.7 RN2.8(N8) RN3.5 RN3.6 RN3.7 RN3.8(N8) RN4.5 RN4.6 RN4.7 RN4.8(N8) RN5.5 RN5.6 RN5.7 RN5.8(N8) RN6.5 RN6.6 RN6.7 RN6.8(N8) RN7.7 RN7.8(N8) U2.6 U2.9(VTT)
XSPI_CLK: R67.2(N2) R110.1 U27.2
XSPI_CS1*: R39.1 R68.1 U27.5
XSPI_CS2*: R40.1 R69.1 U27.9
XSPI_DQ0: R119.2(N2) U22.2
XSPI_DQ1: R118.2(N2) U22.5
XSPI_DQ2: R117.2(N2) U22.9
XSPI_DQ3: R116.2(N2) U22.11
XSPI_DQ4: R115.2(N2) U29.2
XSPI_DQ5: R114.2(N2) U29.5
XSPI_DQ6: R112.2(N2) U29.9
XSPI_DQ7: R111.2(N2) U29.11
XSPI_EN*: R35.2(N2) R36.1 U22.1 U22.4 U22.10 U22.13 U24.13 U27.1 U27.4 U27.10 U27.13 U29.1 U29.4 U29.10 U29.13
XSPI_INT*: R122.1 U25.A5
XSPI_RSTO*: R121.1 U25.A2
XSPI_RWDS: R120.2(N2) U27.11

Pads without a net: D1 6; D17 4 5; J1 27 28 29 30 31 32 33 34 35 36 37 38 48 50 52 54 57 58 59 60 61 62 63 64 65 66 67 68 69 70 71 72 73 74 75 76 77 78 79 80 81 82 83 84 85 86 89 91 93 95 97 99; J2 29 53 54 55 56 57 58 59 60 61 63 64 65 66 67 69 70 72 73 74 75 77; J3 3 4 5 6 7 8 9 10 11 12 13 14 15 16 17 18 19 20 21 23 24 26 27 28 29 30 31 32 33 34 35 37 43 45 47 49 51 53 55 57 59 61 62 63 64 65 66 67 68 69 70 71 72 73 74 75 77 78 79 80 81 82 83 84 86; P1 A2 A3 A8 A10 A11 B2 B3 B8 B10 B11; P6 7; RN7 3 4 5 6; S1 8; U2 5; U4 A2 A3 A5 B1 B5 C1 C3 C5 D1 D5 E1 E2 E3 E4 E5; U8 J1 J9 L1 L9; U15 1 2 10 11 12 13 14 15 16 17 20 21 22 27 28; U18 4; U24 1 2 3 4 11 14 15 24; U25 B1 B5 C5; VR1 5 12 16

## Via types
v1: diameter 0.432, hole 0.203, TOP to BOTTOM, 967 vias
v2: diameter 0.635, hole 0.305, TOP to BOTTOM, 490 vias

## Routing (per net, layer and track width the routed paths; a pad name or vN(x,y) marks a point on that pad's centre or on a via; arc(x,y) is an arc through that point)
DGND: length 436.2
  TOP w0.203: U8.E8 v1(29.82,79.14) ; U8.G8 v1(31.42,79.14) ; U8.G9 v1(31.42,79.94) ; U8.D1 v1(29.02,72.74) ; U1.D2 v1(25.82,58.94) ; U8.E2 v1(29.82,73.54) ; U8.F9 v1(30.62,79.94) ; U8.B1 v1(27.42,72.74) ; U8.P1 v1(37.02,72.74) ; U8.J2 v1(33.02,73.54) ; U8.P9 v1(37.02,79.94) ; U8.D8 v1(29.02,79.14) ; U8.G1 v1(31.42,72.74) ; U8.M9 v1(35.42,79.94) ; U8.B3 v1(27.42,74.34) ; U8.T1 v1(38.62,72.74) ; U8.B9 v1(27.42,79.94) ; U8.T9 v1(38.62,79.94) ; U8.A9 v1(26.62,79.94) ; U8.E1 v1(29.82,72.74) ; U8.J8 v1(33.02,79.14) ; U8.M1 v1(35.42,72.74)
  TOP w0.254: v1(29.72,36.58) 29.6,36.46 U27.7 ; v1(29.72,31.24) 29.6,31.13 U28.7 ; U22.7 23.25,36.46 v1(23.37,36.58) ; v1(36.07,36.58) 35.95,36.46 U29.7 ; v2(32.64,16.26) 32.76,16.14 U16.2 34.16,16.14 34.68,15.62 35.12,15.62 ; U24.19 v2(17.04,63.98) ; P1.B1 27.73,92.22 P1.A12 ; v2(30.54,18.16) 30.54,17.82 U16.10 ; U25.C1 v1(43.29,33.48) ; v1(36.07,31.24) 35.95,31.13 U30.7 ; U23.7 23.25,31.13 v1(23.37,31.24) ; U2.3 v2(55.37,70.68) U2.PAD v2(55.37,71.69) U2.8 ; U25.E5 v1(48.15,31.48) ; v2(33.72,18.16) 33.72,17.82 U16.5 ; U25.B3 v1(46.15,35.34)
  TOP w0.305: C164.2 20.87,50.29 v1(20.62,50.54) ; U1.T4 v1(28.22,48.54) ; U1.N8 v1(30.62,51.74) ; U1.Y20 v1(40.22,45.34) U1.Y19 ; U1.P17 v1(38.62,50.14) ; C45.2 48.64,55.02 v2(48.62,55.04) 46.99,55.04 C44.2 ; U1.N12 v1(33.82,51.74) ; v2(14.29,12.17) R93.2 ; U1.D12 v1(34.62,58.94) ; U1.H10 v1(33.02,54.94) U1.H11 ; U1.R17 v1(38.62,49.34) ; U1.J9 v1(32.22,54.94) ; U1.L12 v1(33.82,53.34) ; U1.H3 v1(26.62,55.74) ; C139.2 v1(32.22,40.94) ; U1.D16 v1(37.82,58.94) ; C79.2 v1(37.02,65.54) ; U1.W19 v1(40.22,46.14) U1.W20 ; C158.2 v2(26.08,89.09) ; C130.2 v1(48.62,62.94) ; v1(48.62,50.14) C67.2 47.87,50.14 ; U1.K9 v1(31.42,54.14) U1.K8 ; U1.G3 v1(26.62,56.54) ; C77.2 v1(48.62,51.74) ; C104.2 v1(20.62,49.14) ; U1.U5 v1(28.22,47.74) ; C81.2 v1(20.64,58.86) ; U1.L8 v1(31.42,53.34) U1.L9 ; C126.2 21.22,62.48 v1(20.15,62.48) ; U1.W2 v1(25.82,46.14) ; S2.4 61.82,34.13 v1(61.85,34.16) ; C91.2 v1(20.62,55.34) ; U1.D17 v1(38.62,58.94) ; U1.N18 v1(39.42,51.74) U1.M18 ; C177.2 47.22,59.54 v2(48.62,59.54) C178.2 48.62,58.72 ; U1.K1 v1(25.02,54.14) ; U1.E18 v1(39.42,58.14) ; v1(45.42,61.34) C134.2 ; P1.B12 33.23,92.22 P1.A1 ; C96.2 v1(20.62,54.14) ; U1.J11 v1(33.02,54.14) ; U1.W1 v1(25.02,46.14) ; 58.23,28.83 58.29,28.77 58.29,28.19 58.04,27.94 58.04,27.42 C182.2 57.92,27.28 57.42,26.78 U14.1 ; 58.23,28.83 v1(58.29,28.83) ; 58.23,28.83 57.34,28.83 U13.3 ; C62.2 v1(45.42,46.94) ; v1(58.04,41.78) 58.04,41.2 C180.2 ; U1.K17 v1(38.62,54.14) ; v1(20.64,57.72) C60.2 ; U1.C16 v1(37.82,59.74) ; U1.Y13 v1(35.42,45.34) ; U1.M11 v1(33.02,51.74) U1.N11 ; U1.Y16 v1(37.82,45.34) ; U1.Y1 v1(25.02,45.34) ; U1.T17 v1(38.62,48.54) ; U1.V3 v1(26.62,46.94) ; U1.M10 v1(33.02,52.54) ; U1.B2 v1(25.82,60.54) ; C129.2 v1(48.62,48.54) ; U1.L17 v1(38.62,52.54) ; U1.C17 v1(38.62,59.74) ; v1(48.63,61.37) 48.62,61.37 48.62,61.34 C146.2 ; v1(38.62,65.54) C84.2 ; C78.2 21.33,47.74 v1(20.62,47.74) ; v1(27.42,40.94) C143.2 ; U1.E3 v1(26.62,58.14) ; v1(45.42,48.54) C82.2 ; U1.J10 v1(32.22,54.14) ; U1.M13 v1(35.42,51.74) ; C150.2 v1(32.26,65.54) ; U1.M8 v1(31.42,52.54) ; U1.M9 v1(32.22,52.54) ; U1.K3 v1(26.62,54.14) ; U1.N13 v1(34.62,51.74) U1.M12 ; U1.J13 v1(34.62,54.94) U1.H13 ; U1.Y7 v1(29.82,45.34) ; C100.2 21.15,52.94 v1(20.62,52.94) ; v2(29.49,19.49) C192.2 ; v1(20.64,61.21) C73.2 ; C116.2 v1(20.62,56.54) ; v1(20.62,63.52) 20.62,63.52 R57.2 ; U1.B19 v1(40.22,60.54) ; U1.H12 v1(33.82,54.94) U1.J12 ; U1.V16 v1(37.82,46.94) ; U1.D4 v1(27.42,58.94) ; C153.2 v1(45.42,62.94) ; U1.V4 v1(27.42,46.94) ; U1.C5 v1(28.22,59.74) ; D15.A v2(26.47,87.38) ; U1.J8 v1(31.42,54.94) ; U1.K10 v1(33.02,53.34) ; U1.C18 v1(39.42,59.74) ; U1.C6 v1(29.02,59.74) ; U1.Y2 v1(25.82,45.34) ; U1.A1 v1(25.02,61.34) ; v2(56.52,9.52) C247.2 55.92,8.57 55.28,9.2 U26.5 ; U1.K12 v1(34.62,54.14) U1.K13 ; C88.2 v1(20.62,46.34) ; C120.2 v1(20.65,60.01) ; U1.H8 v1(31.42,55.74) ; U1.G18 v1(39.42,55.74) U1.H18 ; C149.2 v1(33.82,40.94) ; U1.M17 v1(38.62,51.74) U1.N17 ; C74.2 v1(45.42,58.14) ; U1.V15 v1(37.02,46.94) ; U1.D14 v1(36.22,58.94) ; U1.L11 v1(33.82,52.54) ; U1.H2 v1(25.82,55.74) ; U1.D7 v1(29.82,58.94) ; v2(11.05,74.93) 11.43,75.14 U7.7 ; U1.A20 v1(41.02,61.34) ; C80.2 21.53,41.25 v1(21.22,40.94) ; U1.P1 v1(25.02,50.14) ; U1.L13 v1(34.62,52.54) ; C138.2 v1(45.42,59.74) ; v1(24.22,40.94) C127.2 ; v1(18.99,44.01) C157.2 ; v2(7.37,64.81) R77.2 ; U1.N9 v1(31.42,51.74) ; v2(17.21,9.6) C204.2 ; U1.K2 v1(25.82,54.14) ; U1.J18 v1(39.42,54.94) ; U1.N2 v1(25.82,50.94) ; v2(15.88,86.36) 16.38,86.86 U15.3 ; U1.D5 v1(28.22,58.94) ; v1(35.42,65.54) C69.2 ; v1(45.42,51.74) R58.1 ; U1.L2 v1(25.82,52.54) U1.M1 v1(25.82,51.74) U1.M2 ; U1.H9 v1(32.22,55.74) ; v1(25.82,40.94) C64.2 ; U1.D6 v1(29.02,58.94) ; C83.2 20.8,51.56 v1(20.62,51.74) ; C87.2 v1(48.62,45.34) ; U1.T1 v1(25.02,48.54) ; U1.U16 v1(37.82,47.74) ; D17.2 29.84,88.58 v2(29.53,88.27) ; v2(34.92,19.49) C191.2 ; U1.F3 v1(26.62,57.34) ; U1.K20 v1(41.02,54.14) ; U1.U17 v1(38.62,47.74) ; U1.V18 v1(39.42,46.94) ; U1.P19 v1(40.22,50.14) ; U1.B1 v1(25.02,60.54) ; U1.U1 v1(25.02,47.74) ; v1(33.78,65.54) C110.2 ; U1.L16 v1(37.82,52.54) ; U1.K11 v1(33.82,54.14) ; U1.N10 v1(32.22,51.74) ; U1.P20 v1(41.02,50.14) ; U1.C4 v1(27.42,59.74) ; U1.D15 v1(37.02,58.94) ; U1.C14 v1(36.22,59.74) ; v2(51.31,8.26) U26.2 ; U1.L10 v1(32.22,53.34) ; U1.U4 v1(27.42,47.74) ; U1.D13 v1(35.42,58.94) ; U1.L3 v1(26.62,52.54) ; U1.K18 v1(39.42,54.14) ; U1.C3 v1(26.62,59.74) ; U1.D18 v1(39.42,58.94) ; U4.B3 v1(15.23,33.41) ; U1.F18 v1(39.42,56.54) ; U1.K19 v1(40.22,54.14) ; C135.2 v1(29.02,40.94) ; C229.2 v1(31.53,28.45) ; v2(16.13,9.63) R98.2 ; v1(22.62,40.94) C163.2 ; U1.C15 v1(37.02,59.74) ; U1.Y5 v1(28.22,45.34) ; U1.J3 v1(26.62,54.94) ; v1(45.42,50.14) C133.2 ; C72.2 v1(48.62,46.94) ; C70.2 v1(30.62,40.94) ; U1.R2 v1(25.82,49.34)
  TOP w0.356: C34.2 42.02,72.71 v1(42.02,72.14) 42.02,71.57 C30.2 ; C40.2 42.02,77.97 v1(42.02,78.54) 42.02,79.11 R10.2
  TOP w0.406: v1(29.82,83.34) C5.2 ; v1(32.22,69.44) C32.2 ; C3.2 v1(37.82,83.34) ; v1(37.82,69.41) C8.2 ; v1(54.67,37.39) 55.3,37.39 55.69,37.79 U11.3 ; v1(28.22,69.41) C6.2 ; v1(30.62,69.41) C7.2 ; v2(61.59,67.31) 60.54,67.31 C11.2 60.54,68.07 v2(61.59,68.07) ; v1(34.62,83.34) R4.2 ; v1(28.22,83.34) C1.2 ; C28.2 v1(36.22,83.34) ; v1(32.22,83.34) C2.2
  TOP w0.508: v1(41.15,42.93) 40.38,42.93 R23.2 ; v1(58.04,34.29) 56.54,34.29 S2.1 56.38,32.65 56.77,32.26 C181.2 ; U9.3 17.52,39.5 v2(17.53,39.5) ; D1.2 15.62,92.01 v2(15.62,92.01) D1.5 ; v2(51.69,57.79) C228.2 53.59,57.79 54.74,58.93 U18.2 ; U5.3 v2(13.2,39.5) ; C188.2 v2(13.02,92.44) ; Y1.4 13.21,52.98 v2(13.21,54.36) C168.2 ; R88.2 v2(9.91,87.38) ; R79.2 v2(10.79,46.36) ; v2(47.5,21.59) 47.5,22.28 U20.3 ; Y2.2 v2(15.39,44.7) ; C27.2 v2(52.83,67.71) ; C206.2 23.23,10.29 v2(21.39,10.29) R106.2 ; 3.81,53.72 2.79,53.72 ; C166.2 v2(14.86,49.28) 14.86,50.53 Y1.2 ; U10.3 v2(8.88,39.5) ; C254.2 v2(53.87,67.87) ; C187.2 v2(11.68,93.23) ; U3.3 v2(41.53,25.97) ; C201.2 v2(16.13,47.75) ; U21.3 v2(51.94,21.6) ; P6.5 2.79,52.45 ; R50.2 v1(20.58,31.37) ; v2(16.12,67.56) C179.2 C232.2 ; U19.3 v2(48.45,25.97)
  L3_GND w0.508: 33.28,91.58 P1.B12 33.97,92.27 ; 27.68,91.58 P1.B1 26.99,92.27 ; 2.88,53.72 3.81,53.72 ; 28.48,91.58 P1.GND2 ; 32.48,91.58 P1.GND1 ; 2.88,52.45 P6.5
  L5_SIG w0.508: 28.48,91.58 P1.GND2 ; 27.68,91.58 P1.B1 26.99,92.27 ; 33.28,91.58 P1.B12 33.97,92.27 ; 32.48,91.58 P1.GND1
  L7_SIG w0.508: 26.99,92.27 P1.B1 27.68,91.58 ; 32.48,91.58 P1.GND1 ; 2.88,52.45 P6.5 ; 33.97,92.27 P1.B12 33.28,91.58 ; 28.48,91.58 P1.GND2 ; 2.88,53.72 3.81,53.72
  L9_GND w0.508: 33.28,91.58 P1.B12 33.97,92.27 ; 28.48,91.58 P1.GND2 ; 32.48,91.58 P1.GND1 ; 2.88,52.45 P6.5 ; 2.88,53.72 3.81,53.72 ; 26.99,92.27 P1.B1 27.68,91.58
  BOTTOM w0.14: 27.11,26.1 27.11,26.35 27.75,26.99 27.75,27.43 28.54,28.23 28.54,35.43 29.02,35.9 31.04,35.9 31.79,36.65 31.79,39.3 32.87,40.38 32.87,49 33.02,49.15 v1(33.02,51.74)
  BOTTOM w0.254: 28.48,91.58 P1.GND2 ; 27.68,91.58 P1.B1 ; 33.28,91.58 P1.B12 P1.GND1 32.48,91.58
  BOTTOM w0.305: 41.91,41.34 v1(41.91,40.46) ; v2(14.73,80.52) R84.2 ; v1(5.33,44.2) 5.71,43.94 J3.2 ; v1(38.62,54.14) 38.62,53.45 C112.2 ; C120.2 v1(20.65,60.01) ; v2(37.72,89.6) C42.2 ; v1(20.62,55.34) C91.2 ; v2(16,80.52) C189.2 ; v1(20.62,54.14) C96.2 ; v1(20.62,51.74) 20.8,51.56 C83.2 ; J3.41 2.03,31.24 v1(1.52,31.11) ; C81.2 v1(20.64,58.86) ; J1.44 55.81,26.16 55.5,26.47 v1(55.5,26.8) 55.5,26.8 J1.46 ; C242.2 30.76,54.14 v1(31.42,54.14) ; v1(35.42,51.74) 35.42,51.29 C86.2 ; v1(45.42,50.14) C113.2 ; C131.2 v1(24.22,40.94) ; C95.2 v1(30.62,40.94) ; v1(32.22,51.74) 32.22,51.28 C132.2 ; C115.2 v1(47.31,40.31) ; v1(18.82,56.54) 19.52,56.54 R17.2 ; C244.2 30.76,52.54 v1(31.42,52.54) ; J3.36 5.84,33.15 v1(5.46,33.15) ; C103.2 v1(21.22,40.94) ; v1(45.42,62.94) 44.23,62.94 C94.2 ; C18.2 v1(43.69,75.31) ; C148.2 v1(20.62,47.74) ; v1(20.62,52.94) 21.15,52.94 C100.2 ; v1(20.62,49.14) C104.2 21.37,49.14 ; C14.2 43.69,72.01 v1(43.69,72.01) ; v1(20.62,46.34) C88.2 ; v1(42.52,64.74) 42.52,65.24 C12.2 ; C65.2 27.3,55.74 v1(26.62,55.74) ; v1(35.18,84.96) C10.2 ; v2(42.29,82.55) 42.93,81.91 43.69,81.91 ; C93.2 34.87,53.89 v1(34.62,54.14) ; v1(17.08,44.07) 17.9,44.07 C54.2 ; C97.2 v1(45.42,45.34) ; C150.2 v1(32.26,65.54) ; C85.2 v1(46.23,40.5) ; J3.85 1.91,17.27 v1(1.4,17.27) ; C76.2 38.63,58.14 v1(39.42,58.14) ; J1.55 61.22,29.97 v1(61.72,30.1) ; C143.2 v1(27.42,40.94) ; v1(8.25,37.59) 7.87,37.59 J3.22 ; v2(17.53,39.5) 18.29,40.26 R56.2 ; C128.2 33.82,51.28 v1(33.82,51.74) ; v1(32.22,40.94) C139.2 ; v2(12.38,14.54) 14.45,14.54 R95.1 ; v1(61.72,40.51) 61.21,40.13 J1.87 ; v1(29.02,40.94) C135.2 ; C99.2 v1(25.82,40.94) ; v1(9.14,21.84) 9.14,21.21 8.38,20.45 J3.76 ; v1(28.22,48.54) 28.26,48.58 C147.2 ; C119.2 v1(42.99,40.31) ; J3.39 2.03,31.88 v1(1.52,32) ; v1(8.51,12.7) 8,12.83 J3.100 ; v1(9.4,15.75) 9.02,16 J3.90 ; C48.2 44.73,59.74 v1(45.42,59.74) ; J1.56 57.78,29.97 58.08,29.84 v1(58.24,29.84) ; v1(58.42,26.54) 58.8,26.8 J1.45 ; C60.2 v1(20.64,57.72) ; C163.2 v1(22.62,40.94) ; v1(34.62,51.74) 34.62,51.32 C136.2 ; J3.46 7.87,29.97 v1(8.26,29.84) ; C92.2 v1(48.62,51.74) ; C221.2 C212.2 27.11,25.59 27.11,26.1 ; v1(31.42,55.74) 30.71,55.74 C122.2 ; v2(40.26,82.55) 40.26,83.39 40.56,83.69 C17.2 41.28,83.69 v2(41.28,82.55) ; C152.2 30.62,51.26 v1(30.62,51.74) ; C125.2 v1(48.62,45.34) ; v2(16,73.91) R82.2 ; C164.2 20.87,50.29 v1(20.62,50.54) ; J3.1 2.03,43.94 v1(1.52,44.2) ; C74.2 v1(45.42,58.14) ; v1(48.63,61.37) 48.62,61.37 48.62,61.34 C146.2 ; C73.2 v1(20.64,61.21) ; v2(23.3,100.58) C184.2 ; v1(33.82,40.94) C149.2 ; v1(43.69,82.3) 43.69,81.91 ; 43.69,81.92 C9.2 ; C156.2 32.91,55.74 v1(32.22,55.74) ; v1(58.04,12.83) 57.66,12.83 J1.2 ; J3.98 v1(8.51,13.46) ; C110.2 v1(33.78,65.54) ; v1(45.42,48.54) C145.2 ; C111.2 v1(45.15,40.31) ; v1(58.8,12.83) 59.18,12.83 J1.1 ; C69.2 v1(35.42,65.54) ; v1(61.72,26.29) 61.22,26.16 J1.43 ; v2(36.45,89.6) C246.2 ; v1(20.62,56.54) C116.2 ; v2(35.18,89.6) C43.2 ; C137.2 35.18,55.24 34.87,54.94 v1(34.62,54.94) ; v1(37.02,65.54) C79.2 ; v1(26.62,54.14) 27.35,54.14 C46.2 ; v2(23.3,94.74) R80.2 ; C108.2 31.42,51.3 v1(31.42,51.74) ; v1(1.52,36.45) 1.65,36.32 J3.25 ; C101.2 v1(48.62,46.94) ; J3.60 7.87,25.53 v1(8.26,25.4) ; C105.2 v1(48.62,50.14) ; v2(1.27,69.85) R25.2 ; v1(58.04,41.78) 57.66,42.04 J1.94 ; C130.2 v1(48.62,62.94) ; C16.2 v1(43.69,78.49) ; v1(45.59,63.88) 45.59,64.29 45.34,64.54 44.72,64.54 ; C162.2 v1(20.15,62.48) ; C141.2 v1(48.62,48.54) ; C107.2 v1(44.07,40.46) ; v1(45.42,54.94) R1.2 ; v1(38.62,65.54) C84.2 ; v1(45.42,46.94) C121.2
  BOTTOM w0.381: C253.2 14.28,27.37 v2(13.47,27.37) ; Y6.2 13.46,23.64 v2(13.48,23.62) ; C174.2 v2(10.99,39.46) ; C175.2 v2(20.64,41.09) ; C252.2 13.59,31.62 v2(13.21,31.24) ; R54.2 v2(13.2,39.5)
  BOTTOM w0.406: J2.62 v1(34.97,5.54) ; J2.80 v1(40.69,5.54) ; C238.1 36.07,33.27 v1(36.07,32.51) ; C233.1 23.37,38.6 v1(23.37,37.85) ; J2.71 v1(38.15,4.23) ; v1(29.72,32.51) 29.72,33.27 C236.1 ; J2.48 v1(30.53,7.83) ; C235.1 29.72,38.6 v1(29.72,37.85) ; J2.1 v1(15.92,4.23) ; v1(14.23,34.41) 13.62,34.41 Y4.2 ; J2.24 v1(22.91,5.54) ; C234.1 23.37,33.27 v1(23.37,32.51) ; C237.1 36.07,38.6 v1(36.07,37.85) ; C4.2 v1(48.62,56.54) ; R67.1 v2(42.93,37.08) ; J2.68 v1(36.88,5.54) ; J2.51 v1(31.8,1.94) ; J2.25 v1(23.54,1.94) ; J2.2 v1(15.92,5.54) ; J2.79 v1(40.69,4.23)
  BOTTOM w0.508: C251.2 v2(13.34,37.08) ; C159.2 v2(44.71,28.7) ; v2(51.94,21.6) 52.44,22.1 R34.2 ; v2(48.45,25.97) 49.33,25.97 C160.2 ; R24.2 9.39,80.64 v2(9.65,80.9) ; C55.2 v2(14.86,56.77) ; v1(46.15,35.34) 46.15,36.03 C172.1 ; C50.2 15.86,49.28 16.37,48.77 v2(17.78,48.77) ; C200.1 48.15,30.76 v1(48.15,31.48) ; R36.2 v2(19.43,39.44) ; C183.2 v2(8,87.63) ; v1(43.29,33.48) 44.03,33.48 C199.1 ; P6.5 2.79,52.45 ; C170.2 v2(49.28,25.01) ; 3.81,53.72 2.86,53.72 ; R26.2 v2(1.71,79.69) ; v1(15.23,33.41) 14.72,32.9 C176.2
  vias: v1(1.52,45.34) v1(14.73,90.3) v1(16.49,90.3) v1(21.27,9.33) v1(24.22,56.54) v1(24.64,37.85) v1(24.64,36.58) v1(24.64,32.51) v1(24.64,31.24) v1(30.99,37.85) v1(30.99,36.58) v1(30.99,32.51) v1(30.99,31.24) v1(37.02,25.59) v1(37.34,37.85) v1(37.34,36.58) v1(37.34,32.51) v1(37.34,31.24) v1(38.8,85.03) v1(39.59,20.57) v1(41.91,64.71) v1(42.02,44.14) v1(45.09,14.92) v1(50.04,2.16) v1(50.67,4.44) v1(51.94,46.74) v1(51.94,46.1) v1(52.2,11.43) v1(54.86,45.72) v1(59.94,49.53) v1(59.94,48.51) v1(61.72,42.29) v1(61.72,38.99) v2(1.4,92.96) v2(1.4,62.23) v2(1.4,58.42) v2(1.4,29.34) v2(1.4,27.3) v2(1.52,78.49) v2(1.52,74.8) v2(1.52,71.5) v2(1.52,67.94) v2(2.67,76.83) v2(4.57,73.79) v2(6.73,76.83) v2(6.73,74.55) v2(6.73,71.25) v2(8.26,1.9) v2(9.91,77.6) v2(10.16,67.82) v2(10.54,14.54) v2(10.54,13.78) v2(10.79,25.27) v2(11.3,14.54) v2(11.3,13.78) v2(11.43,5.84) v2(11.68,25.27) v2(12.45,25.27) v2(12.7,1.9) v2(14.48,62.61) v2(14.48,61.34) v2(14.61,87.63) v2(14.61,86.36) v2(14.61,85.09) v2(15.11,61.98) v2(15.75,62.61) v2(15.75,61.34) v2(15.88,87.63) v2(15.88,85.09) v2(17.14,87.63) v2(17.14,86.36) v2(17.14,85.09) v2(17.53,16.26) v2(17.53,15.24) v2(17.53,14.22) v2(18.54,16.26) v2(18.54,15.24) v2(18.54,14.22) v2(22.99,73.66) v2(24.76,25.84) v2(24.76,24.96) v2(24.76,24) v2(24.76,22.42) v2(24.76,21.46) v2(24.76,20.83) v2(24.76,14.61) v2(24.76,13.92) v2(25.4,22.1) v2(25.4,21.46) v2(25.4,20.83) v2(25.59,14.67) v2(25.59,13.92) v2(31.11,83.82) v2(31.62,17.02) v2(31.62,16.26) v2(32.64,17.02) v2(36.58,15.3) v2(38.29,20.13) v2(39.31,27.3) v2(39.31,26.35) v2(39.31,24.7) v2(39.31,23.81) v2(39.31,22.86) v2(39.5,19.68) v2(39.5,18.92) v2(39.5,18.16) v2(40.51,19.68) v2(40.51,18.92) v2(40.51,18.16) v2(41.4,19.68) v2(41.4,18.92) v2(41.4,18.16) v2(42.67,24.76) v2(43.43,24.76) v2(43.43,24) v2(47.18,11.43) v2(48.01,13.33) v2(48.01,11.43) v2(48.58,19.75) v2(48.58,18.99) v2(48.58,18.22) v2(49.53,19.75) v2(49.53,18.99) v2(49.53,18.22) v2(50.16,63.25) v2(51.05,59.94) v2(51.18,63.25) v2(51.18,1.78) v2(51.75,77.79) v2(51.75,77.03) v2(51.75,76.26) v2(51.75,75.5) v2(51.75,74.74) v2(52.51,77.79) v2(52.51,77.03) v2(52.51,76.26) v2(52.51,75.5) v2(52.51,74.74) v2(52.71,87.5) v2(52.71,86.23) v2(52.71,84.96) v2(52.71,83.69) v2(52.83,66.89) v2(53.78,71.44) v2(53.78,70.8) v2(53.98,87.5) v2(53.98,86.23) v2(53.98,84.96) v2(53.98,83.69) v2(54.23,33.65) v2(54.61,71.69) v2(54.61,70.68) v2(55.12,56.9) v2(55.25,87.5) v2(55.25,86.23) v2(55.25,84.96) v2(55.25,83.69) v2(55.25,1.9) v2(56.13,71.69) v2(56.13,70.68) v2(56.52,81.66) v2(57.28,56.9) v2(57.79,81.28) v2(58.55,56.9) v2(58.8,45.21) v2(60.2,77.72) v2(60.2,76.96) v2(60.2,76.2) v2(60.2,75.44) v2(60.2,74.68) v2(60.2,73.91) v2(60.2,65.6) v2(60.33,80.39) v2(60.33,79.12) v2(60.96,77.72) v2(60.96,76.96) v2(60.96,76.2) v2(60.96,75.44) v2(60.96,74.68) v2(60.96,73.91) v2(60.96,65.6) v2(61.22,47.24) v2(61.59,80.39) v2(61.59,79.12) v2(61.59,71.12) v2(61.59,70.36) v2(61.59,69.6) v2(61.59,68.83) v2(61.72,77.72) v2(61.72,76.96) v2(61.72,76.2) v2(61.72,75.44) v2(61.72,74.68) v2(61.72,73.91) v2(61.72,73.15) v2(61.72,72.39) v2(61.72,65.6) v2(61.85,35.56) v2(61.85,32.51)
VDD_CONNECTOR: length 3.7
  BOTTOM w0.305: J3.99 4.19,12.83 v2(4.45,13.08) 4.19,13.46 4.19,13.46 J3.97
  BOTTOM w0.635: v2(4.45,13.08) v2(5.33,13.08)
VDD_DMC: length 72.2
  TOP w0.14: U8.B2 v1(27.42,73.54)
  TOP w0.203: U8.N1 v1(36.22,72.74) ; U1.G13 v1(35.42,56.54) ; U8.K2 v1(33.82,73.54) ; U8.A8 v1(26.62,79.14) ; U8.N9 v1(36.22,79.94) ; U1.G12 v1(34.62,56.54) ; U8.R9 v1(37.82,79.94) ; U8.D9 v1(29.02,79.94) ; U1.F13 v1(35.42,57.34) ; U8.K8 v1(33.82,79.14) ; U8.A1 v1(26.62,72.74) ; U1.F12 v1(34.62,57.34) ; U8.H2 v1(32.22,73.54) ; U8.C1 v1(28.22,72.74) ; U8.C9 v1(28.22,79.94) ; U8.E9 v1(29.82,79.94) ; U8.F1 v1(30.62,72.74) ; U1.F11 v1(33.82,57.34) ; U8.R1 v1(37.82,72.74) ; U8.D2 v1(29.02,73.54) ; U8.G7 v1(31.42,78.34) ; U8.H9 v1(32.22,79.94)
  TOP w0.305: U1.F8 v1(31.42,57.34) U1.F9 ; U1.F14 v1(36.22,57.34) ; U1.F7 v1(29.82,57.34) ; v1(43.02,61.34) C134.1 ; U1.F6 v1(29.02,57.34) ; v1(37.02,63.14) C79.1 ; U1.H7 v1(29.82,55.74) ; U1.G14 v1(36.22,56.54) ; U1.F10 v1(32.22,56.54) ; v1(43.02,58.14) C74.1 ; v1(38.62,63.14) C84.1 ; U1.K7 U1.J7 v1(29.82,54.94) ; v1(46.22,62.94) C130.1 ; U1.G8 v1(31.42,56.54) U1.G9 ; U1.G7 v1(29.82,56.54) ; C126.1 22.47,62.48 v1(23.53,62.48) ; U1.H6 v1(29.02,55.74) ; U1.G15 v1(37.02,56.54) ; R108.1 v2(44.26,10.73) ; U1.G6 v1(29.02,56.54) ; U1.F15 v1(37.02,57.34) ; v1(43.75,58.93) 43.75,59.71 C138.1 ; v1(33.78,63.14) C110.1 ; U1.H14 v1(36.22,55.74) ; v1(35.42,63.14) C69.1 ; U1.J6 v1(29.02,54.94) ; v1(43.02,62.94) C153.1 ; C220.1 v2(45.33,10.73) ; U1.H15 v1(37.02,55.74) ; v1(46.22,61.34) C146.1 ; C150.1 v1(32.26,63.14)
  TOP w0.406: C8.1 v1(37.82,72.74) ; v1(32.22,79.94) 32.22,79.94 C2.1 ; C1.1 28.22,79.94 v1(28.22,79.94) ; R9.1 42.25,75.57 v1(42.02,75.34) 42.25,75.11 C39.1 ; C6.1 v1(28.22,72.74) ; C5.1 v1(29.82,79.94) ; C3.1 v1(37.82,79.94) ; C7.1 v1(30.62,72.74) ; v1(39.22,69.44) R8.1
  L6_PWR w0.508: 40.21,21.35 TP3.1 ; TP3.1 42.34,21.35 ; TP3.1 42.34,23.48 ; TP3.1 40.21,23.48
  BOTTOM w0.305: C102.1 42.72,62.32 43.02,62.63 v1(43.02,62.94) ; v1(31.42,56.54) 30.7,56.54 C122.1 ; v1(38.62,63.14) C84.1 ; J3.92 8.89,15.37 v1(9.4,14.99) ; v1(43.02,61.34) 44.17,61.34 C94.1 ; C150.1 v1(32.26,63.14) ; v1(43.18,64.01) 43.75,64.58 C63.1 ; v1(32.22,56.54) 32.8,56.54 C156.1 ; v1(37.02,63.14) C79.1 ; v1(43.75,58.93) 43.72,58.96 C48.1 ; C162.1 v1(23.53,62.48) ; v1(46.22,62.94) C130.1 ; C74.1 v1(43.02,58.14) ; v1(35.42,63.14) C69.1 ; C110.1 v1(33.78,63.14) ; v1(46.22,61.34) C146.1
  vias: v2(42.8,22.54) v2(42.8,21.84) v2(42.8,21.08) v2(42.8,20.38) v2(43.5,21.84) v2(43.5,21.08) v2(57.66,71.12) v2(57.66,70.36) v2(57.66,68.07) v2(57.66,67.31)
VDD_EXT: length 207.5
  TOP w0.14: U2.7 v1(55.87,73.33)
  TOP w0.254: v1(20.48,13.5) 20.48,13.87 19.86,14.49 VR1.2 ; U29.14 v1(37.45,39.77) ; U25.B4 v1(47.15,35.34) ; U16.4 34.38,17.14 34.53,17.28 ; U27.14 v1(31.1,39.77) ; U23.14 v1(24.75,34.44) ; U28.14 v1(31.1,34.44) ; C232.1 15.36,65.42 U24.21 ; v2(30.48,14.99) 31.13,14.99 31.38,15.24 U16.15 ; U30.14 v1(37.45,34.44) ; 54.87,68.97 U2.2 ; U25.E4 v1(47.15,31.48) ; U25.D1 v1(43.29,32.48) ; U22.14 v1(24.75,39.77)
  TOP w0.267: 54.1,73.79 54.37,73.52 U2.10
  TOP w0.305: C218.1 42.93,14.99 43.1,15.17 U17.8 ; R71.1 59.19,21.21 v1(58.42,21.21) 57.78,21.21 R75.1 ; v1(56.52,7.28) C247.1 55.92,7.94 55.34,7.37 55.08,7.37 55.02,7.3 ; U1.M4 v1(27.42,51.74) ; C80.1 21.53,43.03 v1(21.22,43.34) ; v2(4.45,58.42) DS2.A ; U18.3 56.46,57.98 56.77,58.28 56.77,59.69 56.58,59.88 U18.1 ; U1.N16 v1(37.82,50.94) ; v1(27.42,43.34) C143.1 ; U17.3 47.07,15.17 C215.1 ; U14.4 59.56,25.73 59.56,26.67 58.93,27.3 C182.1 58.92,27.95 v1(58.8,28.07) ; v1(20.62,64.79) R61.1 ; v1(24.22,43.34) C127.1 ; v2(45.71,28.7) 45.71,28.18 45.41,27.87 U3.5 ; U4.B4 v1(13.23,33.41) ; v1(4.45,8.38) R41.1 ; v2(50.28,25.02) 50.28,24.5 49.98,24.19 U20.5 ; U1.U12 v1(34.62,47.74) ; DS5.A v1(57.85,17.25) ; U1.D11 U1.D10 v1(32.22,58.94) ; U1.K4 U1.L4 v1(27.42,52.54) ; v2(5.71,80.9) 5.71,79.02 ; U1.T5 v1(29.02,48.54) ; U1.U15 v1(37.02,47.74) ; U1.U13 v1(35.42,47.74) ; v1(29.02,43.34) C135.1 ; v1(21.15,44.07) 20.63,44.07 C157.1 ; C181.1 58.8,32.25 v1(58.8,31.5) 59.5,30.79 U13.5 ; v2(5.71,68.91) S1.C2 ; U1.U11 v1(33.82,47.74) ; v1(54.88,10.67) R136.1 v1(54.22,11.32) ; U1.U6 v1(29.02,47.74) ; U11.5 59.57,40.4 58.92,41.05 C180.1 58.8,41.2 v1(58.8,41.78) ; v1(22.62,43.34) C163.1 ; R70.1 v1(55.13,30.85) ; 55.02,7.3 55.02,6.03 54.83,5.84 R137.1 v1(54.22,5.19) ; 55.02,7.3 55.02,7.31 U26.4 ; DS6.A 20.19,69.3 v1(20.19,68.58) ; U1.N4 v1(27.42,50.94) ; v2(6.35,58.42) DS1.A ; U1.U10 v1(32.22,47.74) ; U1.M16 v1(37.82,51.74) ; U1.R16 v1(37.82,49.34) ; v1(5.71,8.38) R45.1 ; U1.P16 v1(37.82,50.14) ; U1.U14 v1(36.22,47.74) ; U1.D9 v1(31.42,58.94) U1.D8 ; v2(10.79,47.62) 10.79,47.62 R78.1 ; v2(2.54,58.42) DS3.A ; U7.14 17.27,79.04 v2(16.89,78.74) ; v1(20.62,66.34) R60.1 ; U1.T16 v1(37.82,48.54) ; v2(19.3,9.65) R105.1 ; U1.U8 v1(30.62,47.74) ; U1.P4 v1(27.42,50.14) U1.R4 ; C70.1 v1(30.62,43.34) ; C64.1 v1(25.82,43.34) ; v2(18.22,9.6) C210.1 ; v1(32.22,43.34) C139.1 ; U1.U7 v1(29.82,47.74) ; v2(8.26,58.42) DS4.A ; U1.U9 v1(31.42,47.74)
  TOP w0.381: U9.5 v2(19.82,42.86) ; U5.5 v2(15.5,42.86) ; U10.5 v2(11.18,42.86)
  TOP w0.508: v2(54.23,25.15) 54.24,25.14 U21.5 ; C232.1 C179.1 v2(15.12,67.56) ; v2(50.89,27.42) 50.44,27.87 U19.5 ; R51.1 v1(20.58,36.45) ; R46.1 v1(20.58,33.91) ; R64.1 v2(17.27,67.56) ; R48.1 v1(10.29,32.25) ; 54.87,68.97 C254.1 v2(54.87,67.7) ; R47.1 v1(10.29,36.96)
  L2_PWR w0.508: 55.32,61.74 TP1.1 ; TP1.1 57.45,63.87 ; TP1.1 57.45,61.74 ; TP1.1 55.32,63.87
  L4_SIG w0.381: v2(19.24,25.72) 19.75,25.21 19.75,17.4 20.48,16.66 v1(20.48,13.5) 19.3,12.32 v2(19.3,9.65) 19.25,9.6 v2(18.22,9.6)
  BOTTOM w0.305: C111.1 v1(45.15,42.86) ; v2(49.5,43.84) 49.5,42.9 49.29,42.68 C49.1 48.76,42.68 48.54,42.9 v2(48.54,43.84) ; v2(16.89,78.74) 16,78.74 C189.1 ; v2(13.65,80.77) R83.1 ; C107.1 44.07,41.97 v1(44.07,42.86) ; v1(30.62,43.34) C95.1 ; R81.1 v2(14.73,73.91) ; v1(47.31,42.86) C115.1 ; v2(54.23,25.15) 54.61,24.76 54.61,24.38 C171.1 ; v1(21.15,44.07) 20.33,44.07 C54.1 20.33,44.7 v1(21.15,44.7) ; C139.1 v1(32.22,43.34) ; C131.1 v1(24.22,43.34) ; C119.1 v1(42.99,42.86) ; v1(25.82,43.34) C99.1 ; v1(29.02,48.54) 28.89,48.67 C147.1 ; v1(52.78,40.19) R63.1 R62.1 ; v1(21.22,43.34) C103.1 ; C135.1 v1(29.02,43.34) ; C85.1 v1(46.23,42.9) ; C143.1 v1(27.42,43.34) ; C163.1 v1(22.62,43.34) ; v1(41.91,42.86) 41.91,42.28 C59.1
  BOTTOM w0.381: R55.1 17.21,40.89 16.57,40.26 v2(16.57,39.56) ; v2(16.57,25.72) 16.57,23.25 R143.1 ; v2(16.12,27.37) 15.3,27.37 C253.1 15.31,27.34 Y6.4 ; v2(11.18,42.86) 11.18,42.29 C174.1 ; R53.1 v2(14.29,39.43) ; v2(15.5,42.86) C173.1 ; R140.1 16.92,29.74 v2(17.78,30.61) ; v2(16.64,31.24) 16.26,31.62 C252.1 Y5.4 ; C175.1 v2(19.82,42.86)
  BOTTOM w0.406: v1(31.1,34.44) 30.85,34.19 C236.2 ; v1(32.22,58.94) 32.41,58.75 C90.1 ; v1(24.75,34.44) 24.5,34.19 C234.2 ; R122.2 v1(46.74,39.49) ; v1(24.75,39.77) 24.5,39.52 C233.2 ; C238.2 37.2,34.19 v1(37.45,34.44) ; R39.2 v1(42.16,32.87) ; R121.2 v1(45.72,39.49) ; R40.2 v1(42.93,39.37) ; C237.2 37.2,39.52 v1(37.45,39.77) ; C235.2 30.85,39.52 v1(31.1,39.77)
  BOTTOM w0.508: R139.1 16.29,35.77 Y4.4 15.23,35.8 C251.1 v2(16.13,37.08) ; v2(10.79,47.62) 9.65,48.77 9.65,57.02 v2(8.26,58.42) v2(6.35,58.42) v2(4.45,58.42) v2(2.54,58.42) 2.54,57.91 3.81,56.64 P6.1 ; C200.2 47.15,30.76 v1(47.15,31.48) ; v2(50.28,25.02) C170.1 R14.1 ; R31.1 R32.1 v2(11.68,67.56) ; C160.1 v2(50.89,27.42) ; v2(41.53,13.08) 41.54,13.09 R5.1 ; R15.1 C171.1 ; C176.1 13.72,32.92 v1(13.23,33.41) ; C172.2 47.15,36.03 v1(47.15,35.34) ; R37.1 v2(24.26,29.21) ; R19.1 v2(43.43,28.69) ; C199.2 44.03,32.48 v1(43.29,32.48) ; R35.1 v2(20.57,39.44) ; R33.1 v2(52.44,25.15) ; C159.1 v2(45.71,28.7)
  vias: v2(8.26,6.98) v2(8.26,6.22) v2(10.16,6.98) v2(10.16,6.22) v2(17.46,26.86) v2(17.46,25.72) v2(18.35,26.86) v2(18.35,25.72) v2(19.24,26.86) v2(26.92,16.89) v2(26.92,16.13) v2(27.94,16.89) v2(27.94,16.13) v2(29.21,16.89) v2(29.21,16.13) v2(34.8,16.64) v2(35.56,16.64) v2(36.32,16.64) v2(39.5,13.08) v2(39.5,12.32) v2(39.5,11.56) v2(40.51,13.08) v2(40.51,12.32) v2(40.51,11.56) v2(41.53,12.32) v2(41.53,11.56) v2(52.33,73.41) v2(52.96,73.41) v2(57.91,63.12) v2(57.91,62.36) v2(57.91,61.59) v2(58.67,63.12) v2(58.67,62.36) v2(58.67,61.59)
VDD_INPUT: length 5.5
  BOTTOM w0.305: R96.1 15.62,19.3 12.95,19.3 v2(12.83,19.43)
  vias: v2(10.67,20.19) v2(10.67,19.43) v2(11.81,20.19) v2(11.81,19.43) v2(12.83,20.19) v2(23.24,19.43) v2(24.26,19.43) v2(25.27,19.43)
VDD_INT: length 120.4
  TOP w0.203: U1.H5 v1(28.22,54.94) U1.H4 ; U1.E11 v1(33.82,58.14)
  TOP w0.305: U1.G4 v1(27.42,56.54) ; U1.L5 v1(28.22,52.54) ; U1.M5 v1(28.22,51.74) ; U1.E5 v1(28.22,58.14) ; U1.F16 v1(37.82,57.34) U1.E17 ; v1(23.04,58.86) C81.1 ; v2(32.88,11.81) C208.1 ; v1(23.02,52.94) 22.49,52.94 C100.1 ; U1.R12 v1(34.62,49.34) ; U1.E6 v1(29.02,58.14) ; U1.J17 v1(38.62,54.94) ; U1.H17 v1(38.62,55.74) U1.G17 ; U1.L14 v1(36.22,52.54) U1.L15 v1(37.02,52.54) ; U1.F5 v1(28.22,57.34) ; U1.R13 v1(35.42,49.34) ; v1(23.02,56.54) C116.1 ; U1.J14 v1(36.22,54.94) ; U1.E10 v1(32.22,57.34) ; U1.F17 v1(38.62,56.54) ; U1.E13 v1(35.42,58.14) ; U1.P12 v1(34.62,50.14) ; U1.R6 v1(29.02,50.14) U1.P6 ; C78.1 22.36,47.74 v1(23.02,47.74) ; U1.P7 v1(29.82,50.14) ; v2(34.67,12) R101.1 ; U1.P10 v1(32.22,50.14) ; U1.E7 v1(29.82,58.14) ; U1.E14 v1(36.22,58.14) ; U1.P8 v1(30.62,50.14) ; U1.R7 v1(29.82,49.34) ; U1.H16 v1(37.82,55.74) ; U1.J16 v1(37.82,54.94) ; v1(23.02,51.74) 22.84,51.56 C83.1 ; U1.N14 v1(36.22,51.74) U1.M14 ; U1.R14 v1(36.22,49.34) ; v1(23.02,55.34) C91.1 ; v1(23.04,57.72) C60.1 ; U1.F4 v1(27.42,57.34) ; C209.2 v2(37.21,9.52) ; U1.P11 v1(33.82,50.14) ; R99.2 27.31,14.99 26.92,14.6 v2(26.92,13.59) ; U1.G16 v1(37.82,56.54) ; U1.E16 v1(37.82,58.14) ; U1.E8 v1(30.62,58.14) ; U1.R11 v1(33.82,49.34) ; U1.R8 v1(30.62,49.34) ; U1.M6 v1(29.02,51.74) ; U1.K14 v1(36.22,54.14) ; C164.1 22.77,50.29 v1(23.02,50.54) ; U1.P14 v1(36.22,50.14) ; U1.G5 v1(28.22,56.54) ; R107.2 v2(35.94,9.52) ; U1.E12 v1(34.62,58.14) ; v1(23.02,54.14) C96.1 ; v1(23.05,60.01) C120.1 ; C88.1 v1(23.02,46.34) ; U1.K15 v1(37.02,54.14) ; U1.P13 v1(35.42,50.14) ; v1(23.02,49.14) C104.1 ; U1.J15 v1(37.02,54.94) ; U1.E15 v1(37.02,58.14) ; U1.K16 v1(37.82,54.14) ; U1.R10 v1(32.22,49.34) ; U1.P9 v1(31.42,50.14) ; R44.1 v2(1.91,8.38) ; U1.N6 v1(29.02,50.94) ; v1(23.04,61.21) C73.1 ; U1.E4 v1(27.42,58.14) ; U1.K5 v1(28.22,54.14) U1.J5 ; U1.R9 v1(31.42,49.34) ; U1.N7 v1(29.82,50.94) ; U1.E9 v1(32.22,58.14)
  TOP w0.508: 31.06,27.04 TP2.1 ; TP2.1 33.2,24.91 ; TP2.1 33.2,27.04 ; TP2.1 31.06,24.91
  L2_PWR w0.508: TP2.1 33.2,27.04 ; TP2.1 33.2,24.91 ; TP2.1 31.06,24.91 ; TP2.1 31.06,27.04
  BOTTOM w0.14: v1(33.82,49.34) 33.21,48.73 33.21,40.23 32.13,39.15 32.13,36.51 31.18,35.56 29.16,35.56 28.89,35.29 28.89,28.06 28.13,27.31 28.13,26.98 28.7,26.42 28.7,26.16
  BOTTOM w0.305: v2(1.02,9.91) v2(1.02,9.14) v2(1.02,8.38) v2(1.02,7.62) v2(1.91,7.62) v2(1.91,8.38) ; C86.1 35.42,50.56 v1(35.42,50.14) ; v1(36.22,54.14) 35.87,53.79 C93.1 ; v1(34.62,50.14) 34.62,50.53 C136.1 ; C112.1 37.82,53.43 v1(37.82,54.14) ; C128.1 33.82,50.57 v1(33.82,50.14) ; 28.7,26.16 28.7,25.53 C212.1 ; C120.1 v1(23.05,60.01) ; C100.1 22.49,52.94 v1(23.02,52.94) ; v1(28.22,56.54) 28.22,55.85 C65.1 ; C81.1 v1(23.04,58.86) ; C164.1 22.77,50.29 v1(23.02,50.54) ; C96.1 v1(23.02,54.14) ; C76.1 38.62,57.15 v1(38.62,56.54) ; C148.1 v1(23.02,47.74) ; C116.1 v1(23.02,56.54) ; C108.1 31.42,50.56 v1(31.42,50.14) ; v1(30.62,50.14) 30.62,50.6 C152.1 ; C132.1 32.22,50.57 v1(32.22,50.14) ; C60.1 v1(23.04,57.72) ; v1(23.02,51.74) 22.84,51.56 C83.1 ; C91.1 v1(23.02,55.34) ; v1(23.02,49.14) C104.1 ; C88.1 v1(23.02,46.34) ; C73.1 v1(23.04,61.21)
  BOTTOM w0.508: TP2.1 33.2,24.91 ; TP2.1 31.06,27.04 ; TP2.1 33.2,27.04 ; TP2.1 31.06,24.91 ; L1.1 v2(15.35,55.37) ; C50.1 17.78,50.94 v2(17.78,49.66) ; C55.1 v2(17.79,55.64)
  vias: v2(30.42,25.78) v2(30.86,26.99) v2(30.86,24.13) v2(32.13,24.13) v2(33.4,25.02) v2(33.4,24.13) v2(33.46,26.92) v2(33.85,25.78)
